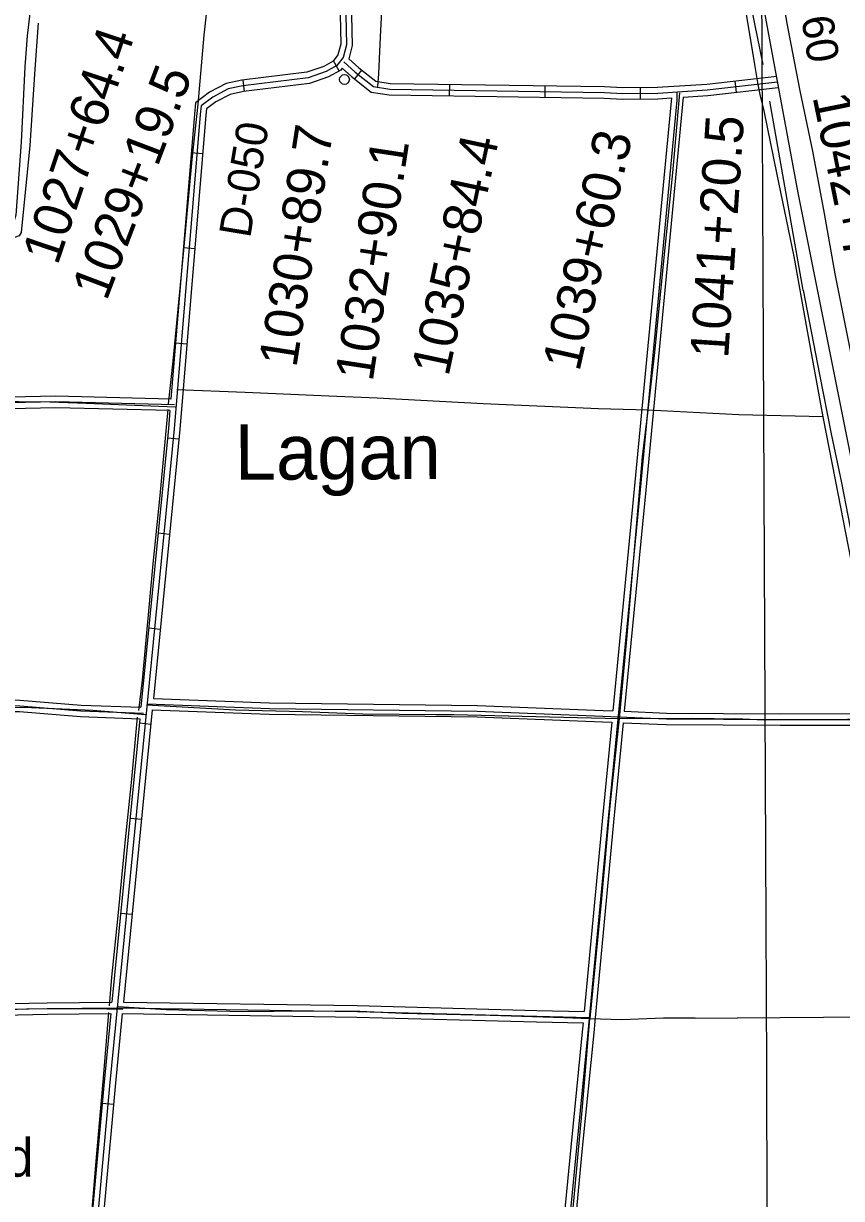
# Model space of a CAD drawing. Extents: x 3424494 to 3462436, y 522220 to 547718.
# Drawn here: x 3442482 to 3444623, y 533824 to 536899 of the extents above; entities that cross this region are included whole.
import ezdxf

# ---------------------------------------------------------------- set-up
doc = ezdxf.new("R2010")
doc.units = 0
for name, color, linetype in [('V-BLDG-IDEN', 7, 'Continuous'), ('V-DOMW-TANK', 7, 'Continuous'), ('V-DTCH-CNTR', 7, 'Continuous'), ('V-GRID-MAJR', 7, 'Continuous'), ('V-RIVR-RANG-IDEN', 7, 'Continuous'), ('V-ROAD-CNTR', 7, 'Continuous'), ('V-SITE-VEGE', 7, 'Continuous'), ('V-SURV-IDEN', 7, 'Continuous'), ('V-TOPO-GNAM-IDEN', 7, 'Continuous'), ('V-TOPO-SHOR', 7, 'Continuous')]:
    doc.layers.add(name, color=color, linetype=linetype)

msp = doc.modelspace()

# ---------------------------------------------------------------- linework, layer by layer
at = {"layer": 'V-DOMW-TANK'}
msp.add_circle((3443321.6803187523, 536752.857468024), 12.846043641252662, dxfattribs=at)
at = {"layer": 'V-DTCH-CNTR'}
for p, q in [((3444574.914, 535870.082), (3444353.98, 535874.735)), ((3442699.4930000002, 534319.859), (3442729.082, 534318.939))]:
    msp.add_line(p, q, dxfattribs=at)
for points in [[(3444352.022, 537025.564), (3444338.966, 537044.76), (3444333.727, 537050.066), (3444323.217, 537055.403), (3444309.3880000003, 537056.812), (3444286.308, 537054.324), (3444208.469, 537042.304), (3444098.9590000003, 537023.899), (3443969.67, 537004.301), (3443787.036, 536989.662), (3443670.365, 536985.14), (3443507.599, 536985.529), (3443456.194, 536985.202), (3443444.987, 536984.616), (3443433.1, 536980.737), (3443424.497, 536974.861), (3443422.486, 536969.604), (3443419.045, 536947.219), (3443415.217, 536864.212), (3443410.64, 536767.37), (3443408.262, 536734.627)], [(3444410.08, 536713.6680000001), (3444404.7970000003, 536739.929), (3444395.8200000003, 536791.729), (3444365.973, 536972.031), (3444352.022, 537025.564)], [(3442520.182, 536900.49), (3442510.841, 536779.955), (3442498.352, 536580.361), (3442475.1380000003, 536352.501), (3442470.467, 536343.305), (3442457.921, 536339.432), (3442425.64, 536340.958), (3442229.397, 536361.991), (3442207.667, 536364.7660000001), (3442200.444, 536368.768), (3442197.1920000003, 536375.379), (3442192.719, 536397.153), (3442189.416, 536498.001), (3442187.687, 536639.034), (3442193.131, 536768.1630000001), (3442191.894, 536780.6900000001), (3442185.346, 536787.324), (3442155.128, 536802.014), (3442141.998, 536810.008), (3442136.114, 536817.294), (3442127.541, 536835.227)], [(3444198.553, 536718.312), (3444180.0700000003, 536508.872), (3444156.12, 536269.153), (3444133.545, 536037.993), (3444115.578, 535887.47), (3444100.951, 535764.991), (3444080.9960000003, 535531.179), (3444059.661, 535288.149), (3444040.502, 535079.937), (3444016.627, 534851.421), (3443993.255, 534599.179), (3443964.305, 534295.156)], [(3445041.254, 533503.759), (3444999.739, 533743.386), (3444942.378, 534018.692), (3444888.024, 534295.291), (3444843.218, 534545.077), (3444781.293, 534838.193), (3444741.299, 535030.828), (3444726.822, 535084.983), (3444705.8710000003, 535205.1950000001), (3444648.255, 535494.714), (3444607.245, 535705.1240000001), (3444574.914, 535870.082), (3444568.485, 535902.879), (3444532.477, 536099.4230000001), (3444498.771, 536289.234), (3444454.258, 536504.4130000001), (3444420.325, 536670.541), (3444410.08, 536713.6680000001)], [(3442878.521, 535895.223), (3442645.585, 535905.0700000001), (3442550.316, 535907.769), (3442387.578, 535909.512), (3442175.436, 535908.0970000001), (3442025.43, 535906.997), (3441888.208, 535911.337), (3441613.5160000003, 535917.278), (3441340.948, 535928.77), (3441216.784, 535928.145), (3441073.671, 535929.916), (3441000.111, 535927.4940000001), (3440894.75, 535926.742), (3440780.6890000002, 535927.475), (3440564.6040000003, 535932.429), (3440485.377, 535941.981), (3440395.028, 535952.301)], [(3444353.98, 535874.735), (3444115.578, 535887.47), (3443986.8510000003, 535891.008), (3443684.38, 535903.389), (3443407.66, 535918.384), (3443281.112, 535924.067), (3443061.386, 535933.134), (3442882.86, 535940.589)], [(3441133.072, 535129.968), (3441168.004, 535131.059), (3441247.08, 535130.551), (3441422.333, 535124.811), (3441554.753, 535118.685), (3441760.3310000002, 535114.726), (3441927.685, 535110.354), (3442034.448, 535110.985), (3442186.012, 535110.667), (3442357.352, 535110.882), (3442502.3170000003, 535109.291), (3442663.0670000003, 535102.326), (3442800.928, 535090.982)], [(3442803.08, 535116.062), (3443036.278, 535102.698), (3443212.199, 535098.2710000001), (3443369.662, 535092.645), (3443560.756, 535090.755), (3443607.543, 535090.453), (3443786.759, 535086.005), (3444040.502, 535079.937), (3444232.205, 535081.16), (3444346.197, 535079.108)], [(3444787.463, 535093.605), (3444765.447, 535091.064), (3444726.822, 535084.983), (3444687.67, 535078.737), (3444588.68, 535076.232), (3444420.296, 535075.755), (3444346.197, 535079.108)], [(3440289.076, 534333.273), (3440397.551, 534329.0970000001), (3440550.54, 534325.331), (3440685.452, 534322.376), (3440842.487, 534315.415), (3440978.931, 534317.704), (3441049.026, 534319.355), (3441130.397, 534318.831), (3441367.5100000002, 534309.653), (3441459.306, 534307.671), (3441590.062, 534307.526), (3441743.799, 534312.101), (3441856.464, 534310.68), (3441984.413, 534306.379), (3442190.972, 534305.0480000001), (3442314.11, 534309.819), (3442389.964, 534316.287), (3442489.45, 534320.514), (3442534.661, 534320.92), (3442699.4930000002, 534319.859)], [(3442729.711, 534325.841), (3442854.8540000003, 534318.081), (3443055.134, 534313.313), (3443218.591, 534315.044), (3443361.861, 534314.12), (3443473.802, 534308.531), (3443702.597, 534303.581), (3443896.608, 534297.464), (3443964.305, 534295.156), (3444047.5, 534292.319), (3444156.724, 534296.485), (3444239.492, 534296.647), (3444349.38, 534295.9400000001)], [(3443894.095, 533523.2710000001), (3443895.281, 533535.86), (3443918.147, 533778.804), (3443945.025, 534063.973), (3443964.305, 534295.156)], [(3444888.024, 534295.291), (3444688.303, 534298.394), (3444349.38, 534295.9400000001)]]:
    msp.add_lwpolyline(points, dxfattribs=at)
at = {"layer": 'V-GRID-MAJR'}
msp.add_spline([(3444456.228, 527681.72), (3444428.916, 533739.1900000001), (3444401.588, 539800.129), (3444374.2600000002, 545861.083), (3444374.244, 545864.536)], degree=3, dxfattribs=at)
at = {"layer": 'V-ROAD-CNTR'}
for p, q in [((3443307.513347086, 536775.108423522), (3443292.899376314, 536801.3083711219)), ((3443059.893842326, 536721.3255310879), (3443056.1418498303, 536751.08947156)), ((3443366.9112282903, 536777.7494182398), (3443348.305265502, 536754.2154653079)), ((3443596.2287696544, 536740.095493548), (3443595.79077053, 536710.0985535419)), ((3443846.201269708, 536736.4455008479), (3443845.7632705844, 536706.4485608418)), ((3444095.767770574, 536731.9395098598), (3444096.018770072, 536701.9405698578)), ((3444343.4182752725, 536748.9184759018), (3444346.8662683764, 536719.1175355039)), ((3442950.4530612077, 536558.6448564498), (3442920.555121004, 536561.113851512)), ((3442929.880102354, 536309.4933547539), (3442899.9821621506, 536311.9623498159)), ((3442909.3071435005, 536060.3418530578), (3442879.408203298, 536062.81084812)), ((3442888.3021855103, 535810.9913517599), (3442858.44724522, 535813.9333458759)), ((3442863.78223455, 535562.19684935), (3442833.92729426, 535565.1388434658)), ((3442839.26228359, 535313.4023469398), (3442809.4073433, 535316.345341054)), ((3442814.743332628, 535064.608844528), (3442784.88739234, 535067.550838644)), ((3442790.2233816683, 534815.814342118), (3442760.36744138, 534818.7563362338)), ((3442765.703430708, 534567.0198397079), (3442735.848490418, 534569.962833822)), ((3442741.1834797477, 534318.2263372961), (3442711.3285394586, 534321.1683314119)), ((3442717.05252801, 534069.515834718), (3442687.174587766, 534072.2188293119))]:
    msp.add_line(p, q, dxfattribs=at)
for points in [[(3444363.01923607, 537177.7766181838), (3444386.2171896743, 537116.404740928), (3444508.6879447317, 536456.3550610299), (3445127.08270794, 533363.1002475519), (3445618.3037254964, 530878.5952165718), (3445629.659702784, 530808.72135632)], [(3443322.0043181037, 537080.4288128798), (3443326.794308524, 536843.7282862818), (3443318.4803251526, 536810.35935302), (3443301.9383582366, 536789.1743953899), (3443273.5304150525, 536773.3294270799), (3443226.4175092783, 536757.432458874), (3443055.208851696, 536735.8535020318), (3443017.31692748, 536728.101517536), (3442976.790008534, 536706.7425602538), (3442946.174069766, 536683.9016059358), (3442943.835074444, 536660.7676522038), (3442875.920210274, 535838.2902971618), (3442706.39254933, 534118.150737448), (3442564.80283251, 532553.4208669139), (3442497.504967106, 531591.130791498), (3442493.14797582, 531491.8599900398), (3442533.963894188, 530671.6396304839)], [(3443307.007348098, 537080.1258134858), (3443311.7573385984, 536845.4192828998), (3443304.6963527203, 536817.078339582), (3443291.982378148, 536800.7963721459), (3443267.428427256, 536787.1013995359), (3443223.048516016, 536772.1264294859), (3443052.763856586, 536750.66447241), (3443012.214937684, 536742.368489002), (3442968.7600245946, 536719.4655348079), (3442931.914098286, 536691.977589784), (3442928.89710432, 536662.1396494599), (3442867.3112274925, 535916.2971411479)], [(3443337.00128811, 537080.731812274), (3443341.83127845, 536842.037289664), (3443333.1462958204, 536807.1773593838)], [(3443315.748330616, 536782.488408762), (3443311.894338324, 536777.552418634), (3443279.6324028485, 536759.557454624), (3443229.78650254, 536742.7384882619), (3443057.653846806, 536721.0425316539), (3443022.4189172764, 536713.8345460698), (3442984.8199924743, 536694.0195856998), (3442960.4340412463, 536675.8256220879), (3442958.773044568, 536659.395654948), (3442890.859180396, 535836.9372998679), (3442821.46231919, 535132.7977081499)], [(3443315.748330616, 536782.488408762), (3443340.2092816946, 536760.615452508), (3443391.500179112, 536720.065533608), (3443438.9850841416, 536712.3885489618), (3444001.34995941, 536704.1765653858), (3444049.575862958, 536701.5525706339), (3444142.0046781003, 536702.325569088), (3444177.5056070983, 536704.5575646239)], [(3443319.9513222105, 536798.8533760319), (3443349.869262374, 536772.100429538), (3443397.7441666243, 536734.2505052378), (3443440.2980815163, 536727.3705189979), (3444001.866958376, 536719.1705353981), (3444049.920862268, 536716.5555406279), (3444141.4706791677, 536717.3215390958), (3444271.4524192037, 536725.4915227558), (3444454.81405248, 536746.7074803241)], [(3443333.1462958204, 536807.1773593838), (3443359.5292430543, 536783.5854065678), (3443403.988154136, 536748.435476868), (3443441.61107889, 536742.352489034), (3444002.3839573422, 536734.16450541), (3444050.2658615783, 536731.558510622), (3444140.936680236, 536732.317509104), (3444270.1194218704, 536740.4374928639), (3444453.090055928, 536761.608450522)], [(3444191.2835795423, 536720.768532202), (3444192.060577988, 536699.1485754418), (3444095.251771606, 535678.8736159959), (3444011.058939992, 534809.9423538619), (3443959.038044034, 534258.5164567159), (3443928.97010417, 533956.644060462), (3443905.8681503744, 533714.1055455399), (3443890.4561811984, 533556.75586024), (3443897.412167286, 533488.6159965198), (3444003.3549554, 532897.0501796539), (3444078.281805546, 532532.656908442), (3444188.390585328, 531983.70900634), (3444241.727478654, 531691.823590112), (3444293.168375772, 531444.3140851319), (3444311.687338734, 531321.1383314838), (3444315.4523312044, 531209.4375548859), (3444313.29433552, 531210.6835523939)], [(3444207.822546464, 536706.4625608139), (3444272.7854165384, 536710.5455526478), (3444456.5380490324, 536731.8065101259)], [(3444177.5056070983, 536704.5575646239), (3444080.31980147, 535680.305613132), (3444024.101913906, 535100.0937735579)], [(3444207.822546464, 536706.4625608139), (3444110.1837417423, 535677.44161886), (3444054.1268538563, 535098.8987759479)], [(3442876.8332084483, 535901.0601716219), (3442565.863830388, 535908.6701564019), (3442326.3873093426, 535903.4791667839), (3442044.6128728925, 535906.9921597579), (3441596.348769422, 535923.8421260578), (3441204.8175524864, 535936.324101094)], [(3442864.838232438, 535886.3492010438), (3442565.8428304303, 535893.66618641), (3442326.456309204, 535888.4771967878), (3442044.2378736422, 535891.9961897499), (3441595.827770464, 535908.85115604), (3441231.0434495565, 535920.4802706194)], [(3442867.3112274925, 535916.2971411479), (3442565.8848303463, 535923.6741263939), (3442326.31830948, 535918.48113678), (3442044.987872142, 535921.988129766), (3442044.357873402, 535922.0121297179)], [(3442864.838232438, 535886.3492010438), (3442860.9812401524, 535839.6432944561), (3442789.0193840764, 535109.473754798)], [(3441150.828006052, 535155.2142881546), (3441490.993980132, 535136.981699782), (3441916.581128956, 535128.3477170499), (3442283.484395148, 535128.889715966), (3442472.2820175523, 535128.0727175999), (3442632.5346970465, 535114.8997439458), (3442789.0193840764, 535109.473754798)], [(3441125.3467114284, 535141.5586906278), (3441490.4399812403, 535121.9897297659), (3441916.440129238, 535113.3477470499), (3442283.4633951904, 535113.889745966), (3442471.6340188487, 535113.0757475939), (3442631.6596987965, 535099.9207739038), (3442795.278371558, 535094.24778525)], [(3441147.6690165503, 535125.3410656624), (3441489.885982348, 535106.9977597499), (3441916.2991295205, 535098.34777705), (3442283.442395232, 535098.889775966), (3442470.986020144, 535098.0787775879), (3442630.7847005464, 535084.9418038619), (3442786.0703899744, 535079.5588146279)], [(3442821.46231919, 535132.7977081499), (3443125.4807111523, 535121.1787313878), (3443669.5516230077, 535114.301745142), (3443998.412965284, 535101.1147715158), (3444024.101913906, 535100.0927735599)], [(3442818.515325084, 535102.8877679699), (3442743.0834759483, 534337.5072987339)], [(3442806.0613499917, 535118.3747369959), (3443125.099711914, 535106.18276138), (3443669.1566237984, 535099.3057751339), (3443997.8139664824, 535086.126801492), (3444164.3386334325, 535079.5018147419), (3444462.506037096, 535077.681818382), (3444654.086653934, 535077.8878179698), (3444745.16347178, 535092.4247888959), (3444776.369409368, 535105.243763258)], [(3442818.515325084, 535102.8877679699), (3443124.7187126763, 535091.1867913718), (3443668.761624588, 535084.3098051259), (3443997.21496768, 535071.1388314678), (3444021.203919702, 535070.184833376)], [(3444051.2278596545, 535068.9898357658), (3444163.9946341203, 535064.503844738), (3444462.468037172, 535062.681848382), (3444655.284651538, 535062.8888479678), (3444749.249463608, 535077.886817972), (3444782.0693979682, 535091.368791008)], [(3444054.125853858, 535098.8987759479), (3444164.682632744, 535094.499784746), (3444462.54403702, 535092.6817883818), (3444652.8886563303, 535092.886787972), (3444741.077479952, 535106.96275982), (3444770.669420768, 535119.118735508)], [(3442786.0703899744, 535079.5588146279), (3442712.948536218, 534337.6172985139)], [(3444021.203919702, 535070.185833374), (3443996.126969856, 534811.370351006), (3443949.11506388, 534313.035347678)], [(3444051.2288596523, 535068.990835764), (3444025.990910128, 534808.5143567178), (3443976.789008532, 534286.9753997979)], [(3439841.621278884, 534337.500298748), (3440171.7436186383, 534330.8773119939), (3440323.17231578, 534335.0383036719), (3440605.352751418, 534324.0713256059), (3440775.29141154, 534309.4343548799), (3440877.0082081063, 534310.542352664), (3441038.4588852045, 534315.2943431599), (3441214.912532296, 534310.5433526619), (3441377.373207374, 534310.2063533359), (3441532.103897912, 534313.3143471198), (3441729.01950408, 534314.6763443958), (3441947.98406615, 534323.4273268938), (3442143.490675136, 534319.2693352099), (3442349.815262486, 534317.178339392), (3442543.731874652, 534320.776332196), (3442725.8955103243, 534322.7573282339), (3443354.625252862, 534313.5723466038), (3443824.9213122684, 534300.7553722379), (3443962.738036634, 534297.732378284)], [(3441065.195365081, 534329.5801662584), (3441215.129531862, 534325.5433226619), (3441377.238207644, 534325.2063233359), (3441531.9008983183, 534328.3133171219), (3441728.668504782, 534329.6743144), (3441947.8440664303, 534338.433296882), (3442143.7256746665, 534334.267305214), (3442349.7522626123, 534332.1793093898), (3442543.5108750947, 534335.7743021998), (3442712.948536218, 534337.6172985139)], [(3442743.0834759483, 534337.5072987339), (3443354.939252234, 534328.5693166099), (3443825.29031153, 534315.7513422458), (3443949.114063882, 534313.0343476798)], [(3441061.96630769, 534299.6555813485), (3441214.6955327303, 534295.5433826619), (3441377.5082071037, 534295.2063833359), (3441532.3068975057, 534298.3153771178), (3441729.370503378, 534299.6783743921), (3441948.1240658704, 534308.421356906), (3442143.255675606, 534304.271365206), (3442349.87826236, 534302.1773693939), (3442543.95287421, 534305.778362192), (3442709.9895421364, 534307.583358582)], [(3442709.9895421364, 534307.583358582), (3442691.458579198, 534119.5617346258), (3442549.8498624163, 532554.6198645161), (3442482.5279970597, 531591.982789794), (3442478.1320058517, 531491.8159901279), (3442518.97792416, 530670.97663181)], [(3442740.131481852, 534307.5483586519), (3442721.3265194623, 534116.73974027), (3442667.6336268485, 533523.3659270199)], [(3442740.131481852, 534307.5483586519), (3443354.31125349, 534298.5753765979), (3443824.5523130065, 534285.75940223), (3443946.2890695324, 534283.0894075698)], [(3443946.2900695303, 534283.090407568), (3443944.108073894, 534259.96445382), (3443914.041134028, 533958.0990575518), (3443890.937180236, 533715.547542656), (3443875.3812113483, 533556.7248603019), (3443878.246205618, 533528.6559164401)], [(3443976.789008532, 534286.9753997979), (3443973.968014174, 534257.0684596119), (3443943.8990743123, 533955.1890633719), (3443920.799120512, 533712.663548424), (3443905.5311510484, 533556.786860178), (3443908.437145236, 533528.3139171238)]]:
    msp.add_lwpolyline(points, dxfattribs=at)
at = {"layer": 'V-SITE-VEGE'}
msp.add_lwpolyline([(3442498.268, 536925.556), (3442490.906, 536866.932), (3442484.7970000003, 536785.95), (3442475.146, 536589.045), (3442461.343, 536397.753), (3442455.629, 536378.234), (3442440.185, 536365.762), (3442419.222, 536364.5), (3442258.681, 536380.898), (3442223.793, 536386.711), (3442214.037, 536389.567), (3442205.697, 536396.606), (3442201.605, 536411.997), (3442198.298, 536548.9180000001), (3442199.43, 536724.9230000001), (3442202.8340000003, 536819.893), (3442203.168, 536871.579), (3442212.128, 536960.925)], dxfattribs=at)
at = {"layer": 'V-TOPO-SHOR'}
msp.add_line((3444522.366, 536201.28), (3444434.696793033, 536695.8709718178), dxfattribs=at)
for points in [[(3444446.619, 537092.265), (3444480.452, 536894.84), (3444513.375, 536723.211), (3444546.426, 536564.9400000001), (3444577.588, 536401.8470000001), (3444605.578, 536244.084), (3444645.6, 536043.607), (3444668.006, 535928.7220000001), (3444696.643, 535790.755), (3444730.306, 535624.187)], [(3443359.5165967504, 536979.143402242), (3443708.746228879, 536980.7180416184), (3443996.7819434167, 536999.4786007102), (3444302.161041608, 537044.5101141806), (3444372.164431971, 537009.9020788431), (3444416.8022855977, 536791.8303886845)], [(3442968.467, 537002.952), (3442953.682, 536868.718), (3442937.9, 536687.857), (3442922.3540000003, 536543.188), (3442899.947, 536305.993), (3442872.327, 536015.936), (3442860.469, 535903.956)], [(3444522.366, 536201.28), (3444565.255, 535980.903), (3444595.609, 535824.975), (3444622.761, 535696.748), (3444655.738, 535525.578), (3444693.329, 535330.151), (3444731.049, 535148.561), (3444740.347, 535107.661)], [(3442859.6750000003, 535888.647), (3442838.046, 535663.975), (3442820.1890000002, 535485.218), (3442792.4760000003, 535180.545), (3442782.918, 535101.261)], [(3442779.326, 535083.884), (3442764.359, 534921.115), (3442747.3340000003, 534763.23), (3442728.648, 534563.595), (3442711.6040000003, 534402.928), (3442705.553, 534327.797)], [(3442704.049, 534310.407), (3442691.188, 534150.407), (3442670.923, 533921.551), (3442651.34, 533690.602), (3442638.063, 533531.424), (3442622.0840000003, 533362.9720000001)]]:
    msp.add_lwpolyline(points, dxfattribs=at)

# ---------------------------------------------------------------- texts
at = {"layer": 'V-BLDG-IDEN'}
msp.add_text('Point Gas and Oil Field', height=99.99980199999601, dxfattribs=at).set_placement((3441132.768696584, 533880.817212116))
at = {"layer": 'V-RIVR-RANG-IDEN'}
for s, rotation, p in [('D-060', 278.70032571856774, (3444490.1747971, 537091.3471716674)), ('D-050', 80.58132571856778, (3443074.69734513, 536335.6808395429))]:
    msp.add_text(s, height=83, rotation=rotation, dxfattribs=at).set_placement(p)
at = {"layer": 'V-SURV-IDEN'}
for s, height, rotation, p in [('1027+64.4', 100.00000000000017, 71.43361112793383, (3442570.6996175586, 536264.0290662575)), ('1029+19.5', 100, 69.19230185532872, (3442698.8701012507, 536170.6916079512)), ('1042+74.7', 100.00000000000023, 281.4739777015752, (3444546.4978087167, 536707.9627124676)), ('1030+89.7', 100.00000000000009, 81.1716183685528, (3443195.7145140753, 535996.5814338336)), ('1041+20.5', 100.00000000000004, 86.2248690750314, (3444325.967606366, 536021.2759439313)), ('1035+84.4', 100.00000000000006, 78.00207030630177, (3443593.7949716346, 535972.9872146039)), ('1039+60.3', 100.00000000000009, 77.3125680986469, (3443936.380181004, 535985.7743649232)), ('1032+90.1', 99.99999999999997, 81.33296681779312, (3443395.3518474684, 535959.8541991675))]:
    msp.add_text(s, height=height, rotation=rotation, dxfattribs=at).set_placement(p)
at = {"layer": 'V-TOPO-GNAM-IDEN'}
msp.add_text('Lagan', height=144.999711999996, rotation=0.22244718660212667, dxfattribs=at).set_placement((3443034.8136586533, 535704.9144860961))

doc.saveas('drawing.dxf')
